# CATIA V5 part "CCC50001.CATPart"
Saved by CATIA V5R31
Part number: CCC50001
Revision: 1
Nomenclature: WELD
Source: Unknown
Property "部品番号(A社)": "CCC50001"
Property "部品名称(A社)": "WELD"
Property "Version(A社)": "1"
Property "材質": "N/A"
Property "板厚": "N/A"
Bounding box of the stored display mesh (mm): x -696.356 to -679.261, y -69.5 to -65, z -15.848 to 9.229
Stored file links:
  \\cad-nas02\CATIA1212\BODY_DEPARTMENT8\JAMA\変換データ\STEP3_最終_20240115\01_いすゞ板金\new_ファイル名修正後\CATIA_V5_20240122\CCC50001.CATPart
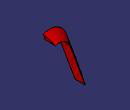
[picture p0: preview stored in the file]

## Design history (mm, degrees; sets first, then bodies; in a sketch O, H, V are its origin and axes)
Set1
  DatumSurface1 "OPEN_SHELL #292"
Body1 "MANIFOLD_SOLID_BREP #331" (main body)
  Solid1: solid without history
